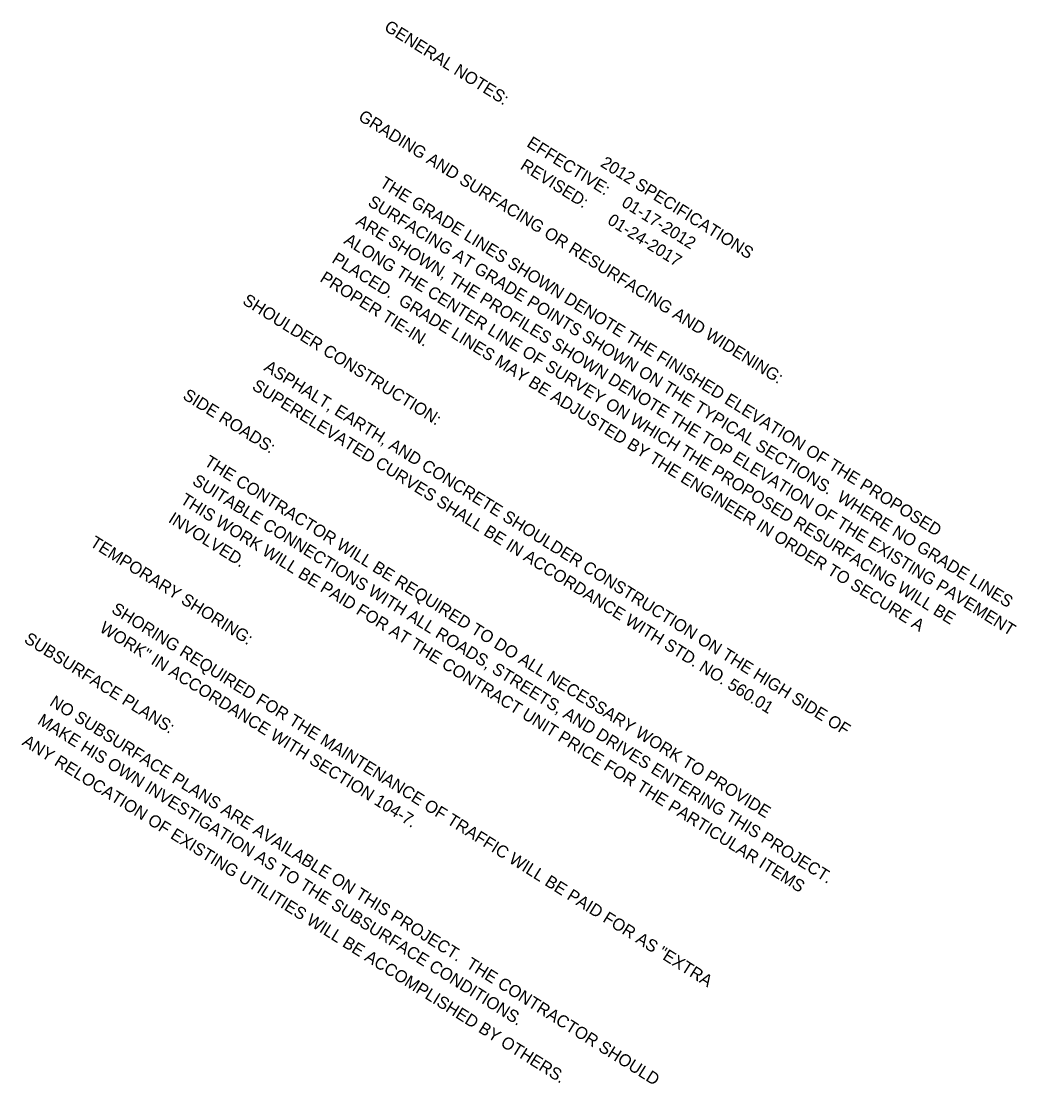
# Model space of a CAD drawing. Extents: x 2337281 to 2340318, y 809513 to 812268.
# Drawn here: x 2338661 to 2339153, y 810837 to 811361 of the extents above; entities that cross this region are included whole.
import ezdxf

# ---------------------------------------------------------------- set-up
doc = ezdxf.new("R2010")
doc.units = 0
doc.layers.add('Default', color=7, linetype='Continuous')

msp = doc.modelspace()

# ---------------------------------------------------------------- texts
at = {"layer": 'Default'}
for s, p in [('GENERAL NOTES:                         2012 SPECIFICATIONS', (2338839.85, 811357.24)), ('GRADING AND SURFACING OR RESURFACING AND WIDENING:  ', (2338827.07, 811312.93)), ('                                       EFFECTIVE:    01-17-2012', (2338836.66, 811346.16)), ('                                       REVISED:      01-24-2017', (2338833.46, 811335.09)), ('         THE GRADE LINES SHOWN DENOTE THE FINISHED ELEVATION OF THE PROPOSED ', (2338820.68, 811290.77)), ('         SURFACING AT GRADE POINTS SHOWN ON THE TYPICAL SECTIONS.  WHERE NO GRADE LINES ', (2338814.78, 811281.4)), ('         ARE SHOWN, THE PROFILES SHOWN DENOTE THE TOP ELEVATION OF THE EXISTING PAVEMENT ', (2338808.87, 811272.02)), ('         ALONG THE CENTER LINE OF SURVEY ON WHICH THE PROPOSED RESURFACING WILL BE ', (2338802.97, 811262.65)), ('         PLACED.  GRADE LINES MAY BE ADJUSTED BY THE ENGINEER IN ORDER TO SECURE A ', (2338797.07, 811253.27)), ('         PROPER TIE-IN.  ', (2338791.17, 811243.9)), ('SHOULDER CONSTRUCTION:  ', (2338769.91, 811222.12)), ('         ASPHALT, EARTH, AND CONCRETE SHOULDER CONSTRUCTION ON THE HIGH SIDE OF', (2338763.52, 811199.96)), ('         SUPERELEVATED CURVES SHALL BE IN ACCORDANCE WITH STD. NO. 560.01', (2338757.62, 811190.58)), ('SIDE ROADS:  ', (2338740.4, 811175.24)), ('         THE CONTRACTOR WILL BE REQUIRED TO DO ALL NECESSARY WORK TO PROVIDE ', (2338734.01, 811153.08)), ('         SUITABLE CONNECTIONS WITH ALL ROADS, STREETS, AND DRIVES ENTERING THIS PROJECT.  ', (2338728.11, 811143.71)), ('         THIS WORK WILL BE PAID FOR AT THE CONTRACT UNIT PRICE FOR THE PARTICULAR ITEMS ', (2338722.21, 811134.33)), ('         INVOLVED.  ', (2338716.31, 811124.96)), ('TEMPORARY SHORING:  ', (2338694.61, 811102.49)), ('         SHORING REQUIRED FOR THE MAINTENANCE OF TRAFFIC WILL BE PAID FOR AS "EXTRA ', (2338688.22, 811080.33)), ('         WORK" IN ACCORDANCE WITH SECTION 104-7.  ', (2338682.32, 811070.96)), ('SUBSURFACE PLANS:  ', (2338662.04, 811054.95)), ('         NO SUBSURFACE PLANS ARE AVAILABLE ON THIS PROJECT.  THE CONTRACTOR SHOULD ', (2338657.68, 811034.45)), ('         MAKE HIS OWN INVESTIGATION AS TO THE SUBSURFACE CONDITIONS.  ', (2338651.72, 811025.38)), ('         ANY RELOCATION OF EXISTING UTILITIES WILL BE ACCOMPLISHED BY OTHERS.  ', (2338644.13, 811014.95))]:
    msp.add_text(s, height=6, rotation=327.8134, dxfattribs=at).set_placement(p)

doc.saveas('drawing.dxf')
